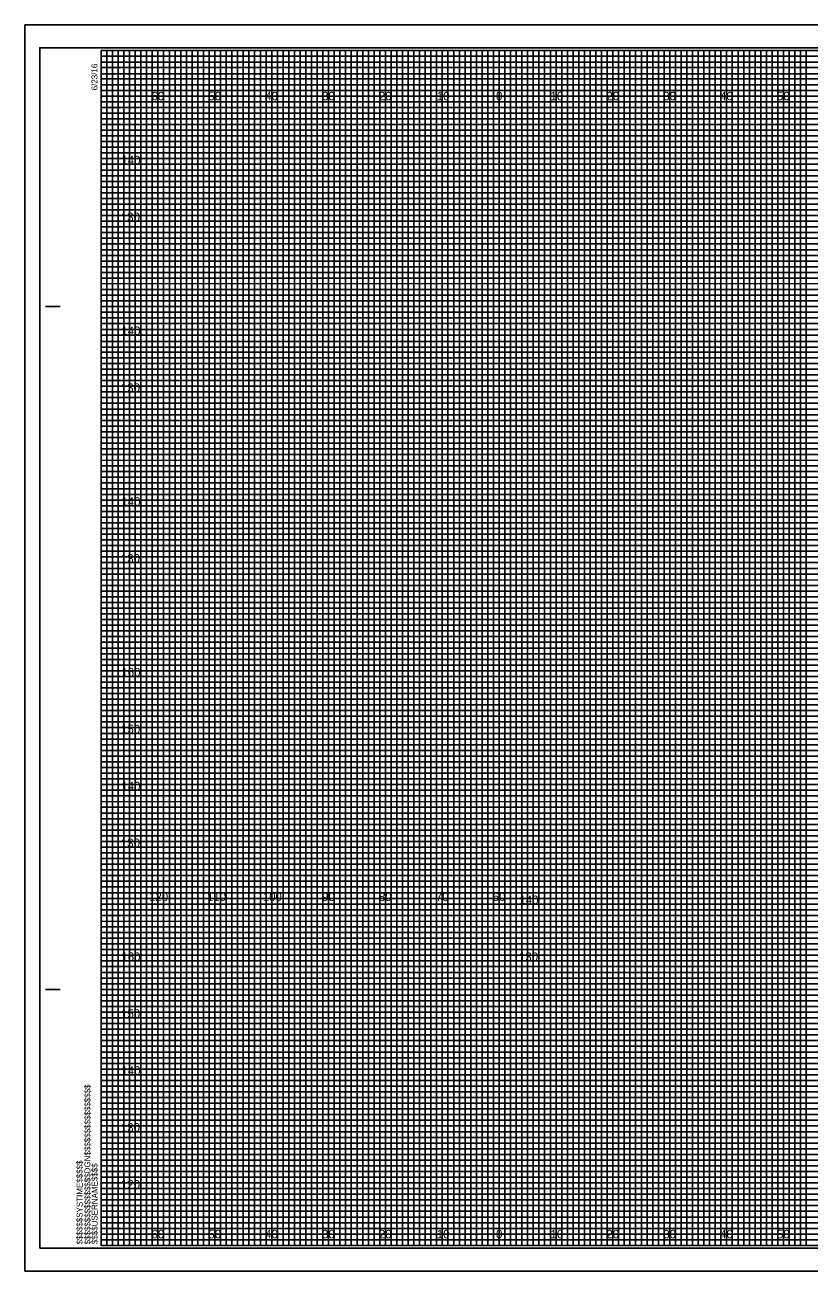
# Model space of a CAD drawing. Extents: x -13 to 323, y -5 to 3294.
# Drawn here: x -13.4 to 124.5, y 1535.5 to 1754.5 of the extents above; entities that cross this region are included whole.
import ezdxf

# ---------------------------------------------------------------- set-up
doc = ezdxf.new("R2010")
doc.units = 0
for name, color, linetype in [('Default', 7, 'Continuous'), ('Prop XS Elevation Labels', 7, 'Continuous'), ('Prop XS Offset Labels', 7, 'Continuous'), ('Scratch_Level_0', 7, 'Continuous'), ('Sheet Cross Section CELL', 7, 'Continuous'), ('Sheet Cross Section Grid Major CELL', 7, 'Continuous'), ('Sheet Cross Section Grid Middle CELL', 7, 'Continuous'), ('Sheet Cross Section Grid Minor 1 CELL', 7, 'Continuous'), ('Sheet Cross Section Grid Minor 2 CELL', 7, 'Continuous'), ('Sheet Cutting Line CELL', 7, 'Continuous'), ('Sheet DOT Grid CELL', 7, 'Continuous'), ('Sheet Plot Border Inside CELL', 7, 'Continuous'), ('Sheet Plot Border Outside CELL', 7, 'Continuous')]:
    doc.layers.add(name, color=color, linetype=linetype)

msp = doc.modelspace()

# ---------------------------------------------------------------- linework, layer by layer
at = {"layer": 'Default'}
msp.add_lwpolyline([(70, 1600), (10, 1600), (10, 1585), (70, 1585)], close=True, dxfattribs=at)
at = {"layer": 'Scratch_Level_0'}
for points in [[(310, 1730), (10, 1730), (10, 1710), (310, 1710)], [(310, 1700), (10, 1700), (10, 1680), (310, 1680)], [(310, 1670), (10, 1670), (10, 1650), (310, 1650)], [(315, 1640), (10, 1640), (10, 1605), (315, 1605)], [(310, 1590), (10, 1590), (10, 1555), (310, 1555)]]:
    msp.add_lwpolyline(points, close=True, dxfattribs=at)
at = {"layer": 'Sheet Cross Section CELL'}
for p, q in [((-9.8, 1705), (-7.3, 1705)), ((-9.7, 1705), (-7.2, 1705)), ((-9.8, 1585), (-7.3, 1585)), ((-9.7, 1585), (-7.2, 1585)), ((0, 1540), (0, 1540)), ((0, 1540), (0, 1540)), ((0, 1540), (0, 1540)), ((0, 1540), (0, 1540)), ((0, 1540), (0, 1540)), ((0, 1540), (0, 1540)), ((0, 1540), (0, 1540))]:
    msp.add_line(p, q, dxfattribs=at)
msp.add_lwpolyline([(320, 1750), (0, 1750), (0, 1540), (320, 1540)], close=True, dxfattribs=at)
at = {"layer": 'Sheet Cross Section Grid Major CELL'}
for p, q in [((10, 1750), (0, 1750)), ((10, 1540), (10, 1750)), ((30, 1750), (20, 1750)), ((20, 1750), (20, 1540)), ((30, 1540), (30, 1750)), ((50, 1750), (40, 1750)), ((40, 1750), (40, 1540)), ((50, 1540), (50, 1750)), ((70, 1750), (60, 1750)), ((60, 1750), (60, 1540)), ((70, 1540), (70, 1750)), ((90, 1750), (80, 1750)), ((80, 1750), (80, 1540)), ((90, 1540), (90, 1750)), ((110, 1750), (100, 1750)), ((100, 1750), (100, 1540)), ((110, 1540), (110, 1750)), ((130, 1750), (120, 1750)), ((120, 1750), (120, 1540)), ((20, 1540), (10, 1540)), ((40, 1540), (30, 1540)), ((60, 1540), (50, 1540)), ((80, 1540), (70, 1540)), ((100, 1540), (90, 1540)), ((120, 1540), (110, 1540))]:
    msp.add_line(p, q, dxfattribs=at)
for points in [[(0, 1740), (320, 1740), (320, 1730), (0, 1730)], [(0, 1720), (320, 1720), (320, 1710), (0, 1710)], [(0, 1700), (320, 1700), (320, 1690), (0, 1690)], [(0, 1680), (320, 1680), (320, 1670), (0, 1670)], [(0, 1660), (320, 1660), (320, 1650), (0, 1650)], [(0, 1640), (320, 1640), (320, 1630), (0, 1630)], [(0, 1620), (320, 1620), (320, 1610), (0, 1610)], [(0, 1600), (320, 1600), (320, 1590), (0, 1590)], [(0, 1580), (320, 1580), (320, 1570), (0, 1570)], [(0, 1560), (320, 1560), (320, 1550), (0, 1550)]]:
    msp.add_lwpolyline(points, dxfattribs=at)
at = {"layer": 'Sheet Cross Section Grid Middle CELL'}
for points in [[(0, 1750), (5, 1750), (5, 1540), (15, 1540), (15, 1750), (25, 1750), (25, 1540), (35, 1540), (35, 1750), (45, 1750), (45, 1540), (55, 1540), (55, 1750), (65, 1750), (65, 1540), (75, 1540), (75, 1750), (85, 1750), (85, 1540), (95, 1540), (95, 1750), (105, 1750), (105, 1540), (115, 1540), (115, 1750), (125, 1750)], [(0, 1745), (275, 1745)], [(0, 1725), (320, 1725), (320, 1735), (0, 1735)], [(0, 1705), (320, 1705), (320, 1715), (0, 1715)], [(0, 1685), (320, 1685), (320, 1695), (0, 1695)], [(0, 1665), (320, 1665), (320, 1675), (0, 1675)], [(0, 1645), (320, 1645), (320, 1655), (0, 1655)], [(0, 1625), (320, 1625), (320, 1635), (0, 1635)], [(0, 1605), (320, 1605), (320, 1615), (0, 1615)], [(0, 1585), (320, 1585), (320, 1595), (0, 1595)], [(0, 1565), (320, 1565), (320, 1575), (0, 1575)], [(0, 1545), (320, 1545), (320, 1555), (0, 1555)]]:
    msp.add_lwpolyline(points, dxfattribs=at)
at = {"layer": 'Sheet Cross Section Grid Minor 1 CELL'}
for p, q in [((0, 1749), (260, 1749)), ((260, 1747.98), (0, 1747.98)), ((0, 1747.98), (0, 1747)), ((0, 1747), (260, 1747)), ((260, 1745.89), (0, 1745.89)), ((0, 1745.89), (0, 1744)), ((0, 1744), (320, 1744))]:
    msp.add_line(p, q, dxfattribs=at)
for points in [[(0, 1743), (270, 1743), (320, 1743), (320, 1742), (0, 1742)], [(0, 1741), (320, 1741), (320, 1739), (0, 1739)], [(0, 1738), (320, 1738), (320, 1737), (0, 1736.98)], [(0, 1736), (320, 1736), (320, 1734), (0, 1734)], [(0, 1733), (320, 1733), (320, 1732), (0, 1732)], [(0, 1731), (320, 1731), (320, 1729), (0, 1729)], [(0, 1728), (320, 1728), (320, 1727), (0, 1727)], [(0, 1726), (320, 1726), (320, 1724), (0, 1724)], [(0, 1723), (320, 1723), (320, 1722), (0, 1722)], [(0, 1721), (320, 1721), (320, 1719), (0, 1719)], [(0, 1718), (320, 1718), (320, 1717), (0, 1717)], [(0, 1716), (320, 1716), (320, 1713.95), (320, 1713), (320, 1712), (0, 1712)], [(0, 1714), (320, 1714), (320, 1713), (0, 1713)], [(0, 1711), (320, 1711), (320, 1709), (0, 1709.03)], [(0, 1709.03), (320, 1709), (320, 1708), (0, 1708)], [(0, 1707), (320, 1707), (320, 1706), (0, 1706)], [(0, 1704), (320, 1704), (320, 1703), (0, 1703)], [(0, 1702), (320, 1702), (320, 1701), (0, 1701)], [(-0.07, 1698.89), (320, 1698.89), (320, 1697.88), (-0.07, 1697.88)], [(0, 1697), (320, 1697), (320, 1696), (0, 1696)], [(0, 1694), (320, 1694), (320, 1693), (0, 1693)], [(0, 1692), (320, 1692), (320, 1691), (0, 1691)], [(0, 1689), (320, 1689), (320, 1688), (0, 1688)], [(0, 1687), (320, 1687), (320, 1686), (0, 1686)], [(0, 1684), (320, 1684), (320, 1683), (0, 1683)], [(0, 1682), (320, 1682), (320, 1681), (0, 1681)], [(0, 1679), (320, 1679), (319.99, 1677.98), (0, 1678)], [(0, 1677), (320, 1677), (320, 1676), (0, 1676)], [(0, 1674), (320, 1674), (320, 1673), (0, 1673)], [(0, 1672), (320, 1672), (320, 1671), (0, 1671)], [(0, 1669), (320, 1669), (320, 1668), (0, 1668)], [(0, 1667), (320, 1667), (320, 1666), (0, 1666)], [(0, 1664), (320, 1664), (320, 1663), (0, 1663)], [(0, 1662), (320, 1662), (320, 1661), (0, 1661)], [(0, 1659), (320, 1659), (320, 1658), (0, 1658)], [(0, 1656.99), (320.07, 1656.91), (320, 1656), (0, 1656)], [(0, 1654), (320, 1654), (320, 1653), (0, 1653)], [(0, 1652), (320, 1652), (320, 1651), (0, 1651)], [(0, 1649), (320, 1649), (320, 1648), (0, 1648)], [(0, 1647), (320, 1647), (320, 1646), (0, 1646)], [(0, 1644), (320, 1644), (320, 1643), (0, 1643)], [(0, 1642), (320, 1642), (320, 1641), (0, 1641)], [(0, 1639), (320, 1639), (320, 1638), (0, 1638)], [(0, 1637), (320, 1637), (320, 1636), (0, 1636)], [(0, 1634), (320, 1634), (320, 1633), (0, 1633)], [(0, 1632), (320, 1632), (320, 1631), (0, 1631)], [(0, 1629), (320, 1629), (320, 1628), (0, 1628)], [(0, 1627), (320, 1627), (320, 1626), (0, 1626)], [(0, 1624), (320, 1624), (320, 1623), (0, 1623)], [(0, 1622), (320, 1622), (320, 1621), (0, 1621)], [(0, 1619), (320, 1619), (319.99, 1617.98), (0, 1618)], [(0, 1617), (320, 1617), (320, 1616), (0, 1616)], [(0, 1614), (320, 1614), (320, 1613), (0, 1613)], [(0, 1612), (320, 1612), (320, 1611), (0, 1611)], [(0, 1609), (320, 1609), (320, 1608), (0, 1608)], [(0, 1607), (320, 1607), (320, 1606), (0, 1606)], [(0, 1604), (320, 1604), (320, 1603), (0, 1603)], [(0, 1602), (320, 1602), (320, 1601), (0, 1601)], [(0, 1599), (320, 1599), (320, 1598), (0, 1598)], [(0, 1596.99), (320.07, 1596.91), (320, 1596), (0, 1596)], [(0, 1594), (320, 1594), (320, 1593), (0, 1593)], [(0, 1592), (320, 1592), (320, 1591), (0, 1591)], [(0, 1589), (320, 1589), (320, 1588), (0, 1588)], [(0, 1587), (320, 1587), (320, 1586), (0, 1586)], [(0, 1584), (320, 1584), (320, 1583), (0, 1583)], [(0, 1582), (320, 1582), (320, 1581), (0, 1581)], [(0, 1579), (320, 1579), (320, 1578), (0, 1578)], [(0, 1577), (320, 1577), (320, 1576), (0, 1576)], [(0, 1574), (320, 1574), (320, 1573), (0, 1573)], [(0, 1572), (320, 1572), (320, 1571), (0, 1571)], [(0, 1569), (320, 1569), (320, 1568), (0, 1568)], [(0, 1567), (320, 1567), (320, 1566), (0, 1566)], [(0, 1564), (320, 1564), (320, 1563), (0, 1563)], [(0, 1562), (320, 1562), (320, 1561), (0, 1561)], [(0, 1559), (320, 1559), (320, 1558), (0, 1558)], [(0, 1557), (320, 1557), (320, 1556), (0, 1556)], [(0, 1554), (320, 1554), (320, 1553), (0, 1553)], [(0, 1552), (320, 1552), (320, 1551), (0, 1551)], [(0, 1549), (320, 1549), (320, 1548), (0, 1548)], [(0, 1547), (320, 1547), (320, 1546), (0, 1546)], [(0, 1544), (320, 1544), (320, 1543), (0, 1543)], [(0, 1542), (320, 1542), (320, 1541), (0, 1541)]]:
    msp.add_lwpolyline(points, dxfattribs=at)
at = {"layer": 'Sheet Cross Section Grid Minor 2 CELL'}
for points in [[(0, 1540), (1, 1540), (1, 1750), (2, 1750), (2, 1540)], [(2, 1540), (3, 1540), (3, 1750), (4, 1750), (4, 1540)], [(5, 1540), (6, 1540), (6, 1750), (7, 1750), (7, 1540)], [(7, 1540), (8, 1540), (8, 1750), (9, 1750), (9, 1540)], [(10, 1540), (11, 1540), (11, 1750), (12, 1750), (12, 1540)], [(12, 1540), (13, 1540), (13, 1750), (14, 1750), (14, 1540)], [(15, 1540), (16, 1540), (16, 1750), (17, 1750), (17, 1540)], [(17, 1540), (18, 1540), (18, 1750), (19, 1750), (19, 1540)], [(20, 1540), (21, 1540), (21, 1750), (22, 1750), (22, 1540)], [(22, 1540), (23, 1540), (23, 1750), (24, 1750), (24, 1540)], [(25, 1540), (26, 1540), (26, 1750), (27, 1750), (27, 1540)], [(27, 1540), (28, 1540), (28, 1750), (29, 1750), (29, 1540)], [(30, 1540), (31, 1540), (31, 1750), (32, 1750), (32, 1540)], [(32, 1540), (33, 1540), (33, 1750), (34, 1750), (34, 1540)], [(35, 1540), (36, 1540), (36, 1750), (37, 1750), (37, 1540)], [(37, 1540), (38, 1540), (38, 1750), (39, 1750), (39, 1540)], [(40, 1540), (41, 1540), (41, 1750), (42, 1750), (42, 1540)], [(42, 1540), (43, 1540), (43, 1750), (44, 1750), (44, 1540)], [(45, 1540), (46, 1540), (46, 1750), (47, 1750), (47, 1540)], [(47, 1540), (48, 1540), (48, 1750), (49, 1750), (49, 1540)], [(50, 1540), (51, 1540), (51, 1750), (52, 1750), (52, 1540)], [(52, 1540), (53, 1540), (53, 1750), (54, 1750), (54, 1540)], [(55, 1540), (56, 1540), (56, 1750), (57, 1750), (57, 1540)], [(57, 1540), (58, 1540), (58, 1750), (59, 1750), (59, 1540)], [(60, 1540), (61, 1540), (61, 1750), (62, 1750), (62, 1540)], [(62, 1540), (63, 1540), (63, 1750), (64, 1750), (64, 1540)], [(65, 1540), (66, 1540), (66, 1750), (67, 1750), (67, 1540)], [(67, 1540), (68, 1540), (68, 1750), (69, 1750), (69, 1540)], [(70, 1540), (71, 1540), (71, 1750), (72, 1750), (72, 1540)], [(72, 1540), (73, 1540), (73, 1750), (74, 1750), (74, 1540)], [(75, 1540), (76, 1540), (76, 1750), (77, 1750), (77, 1540)], [(77, 1540), (78, 1540), (78, 1750), (79, 1750), (79, 1540)], [(80, 1540), (81, 1540), (81, 1750), (82, 1750), (82, 1540)], [(82, 1540), (83, 1540), (83, 1750), (84, 1750), (84, 1540)], [(85, 1540), (86, 1540), (86, 1750), (87, 1750), (87, 1540)], [(87, 1540), (88, 1540), (88, 1750), (89, 1750), (89, 1540)], [(90, 1540), (91, 1540), (91, 1750), (92, 1750), (92, 1540)], [(92, 1540), (93, 1540), (93, 1750), (94, 1750), (94, 1540)], [(95, 1540), (96, 1540), (96, 1750), (97, 1750), (97, 1540)], [(97, 1540), (98, 1540), (98, 1750), (99, 1750), (99, 1540)], [(100, 1540), (101, 1540), (101, 1750), (102, 1750), (102, 1540)], [(102, 1540), (103, 1540), (103, 1750), (104, 1750), (104, 1540)], [(105, 1540), (106, 1540), (106, 1750), (107, 1750), (107, 1540)], [(107, 1540), (108, 1540), (108, 1750), (109, 1750), (109, 1540)], [(110, 1540), (111, 1540), (111, 1750), (112, 1750), (112, 1540)], [(112, 1540), (113, 1540), (113, 1750), (114, 1750), (114, 1540)], [(115, 1540), (116, 1540), (116, 1750), (117, 1750), (117, 1540)], [(117, 1540), (118, 1540), (118, 1750), (119, 1750), (119, 1540)], [(120, 1540), (121, 1540), (121, 1750), (122, 1750), (122, 1540)], [(122, 1540), (123, 1540), (123, 1750), (124, 1750), (124, 1540)]]:
    msp.add_lwpolyline(points, dxfattribs=at)
at = {"layer": 'Sheet Cutting Line CELL'}
for p, q in [((323.3, 1754.5), (-13.4, 1754.5)), ((-13.4, 1754.5), (-13.4, 1535.5)), ((-13.4, 1535.5), (323.3, 1535.5))]:
    msp.add_line(p, q, dxfattribs=at)
at = {"layer": 'Sheet DOT Grid CELL'}
for p, q in [((10, 1540), (10, 1750)), ((20, 1540), (20, 1750)), ((30, 1540), (30, 1750)), ((40, 1540), (40, 1750)), ((50, 1540), (50, 1750)), ((60, 1540), (60, 1750)), ((70, 1540), (70, 1750)), ((80, 1540), (80, 1750)), ((90, 1540), (90, 1750)), ((100, 1540), (100, 1750)), ((110, 1540), (110, 1750)), ((120, 1540), (120, 1750)), ((0, 1740), (320, 1740)), ((0, 1730), (320, 1730)), ((0, 1720), (320, 1720)), ((0, 1710), (320, 1710)), ((0, 1700), (320, 1700)), ((0, 1690), (320, 1690)), ((0, 1680), (320, 1680)), ((0, 1670), (320, 1670)), ((0, 1660), (320, 1660)), ((0, 1650), (320, 1650)), ((0, 1640), (320, 1640)), ((0, 1630), (320, 1630)), ((0, 1620), (320, 1620)), ((0, 1610), (320, 1610)), ((0, 1600), (320, 1600)), ((0, 1590), (320, 1590)), ((0, 1580), (320, 1580)), ((0, 1570), (320, 1570)), ((0, 1560), (320, 1560)), ((0, 1550), (320, 1550))]:
    msp.add_line(p, q, dxfattribs=at)
at = {"layer": 'Sheet Plot Border Inside CELL'}
msp.add_lwpolyline([(-10.8, 1539.5), (322.4, 1539.5), (322.4, 1750.5), (-10.8, 1750.5)], close=True, dxfattribs=at)
at = {"layer": 'Sheet Plot Border Outside CELL'}
msp.add_lwpolyline([(-13.4, 1535.5), (323.3, 1535.5), (323.3, 1754.5), (-13.4, 1754.5)], close=True, dxfattribs=at)

# ---------------------------------------------------------------- texts
at = {"layer": 'Prop XS Elevation Labels'}
for s, p in [('140', (3.57, 1730)), ('130', (3.49, 1720)), ('140', (3.57, 1700)), ('130', (3.49, 1690)), ('140', (3.57, 1670)), ('130', (3.49, 1660)), ('160', (3.57, 1640)), ('150', (3.52, 1630)), ('140', (3.57, 1620)), ('130', (3.49, 1610)), ('140', (73.57, 1600)), ('160', (3.57, 1590)), ('130', (73.49, 1590)), ('150', (3.52, 1580)), ('140', (3.57, 1570)), ('130', (3.49, 1560)), ('120', (3.5, 1550))]:
    msp.add_text(s, height=1.5, dxfattribs=at).set_placement(p)
at = {"layer": 'Prop XS Offset Labels'}
for s, p in [('60', (8.86, 1741.25)), ('50', (18.86, 1741.25)), ('40', (28.86, 1741.25)), ('30', (38.86, 1741.25)), ('20', (48.86, 1741.25)), ('10', (59.04, 1741.25)), ('0', (69.45, 1741.25)), ('0', (69.45, 1741.25)), ('10', (79.04, 1741.25)), ('20', (88.86, 1741.25)), ('30', (98.86, 1741.25)), ('40', (108.86, 1741.25)), ('50', (118.86, 1741.25)), ('120', (8.44, 1600.52)), ('110', (18.62, 1600.52)), ('100', (28.44, 1600.52)), ('90', (38.86, 1600.52)), ('80', (48.86, 1600.52)), ('70', (58.86, 1600.52)), ('60', (68.86, 1600.52)), ('60', (8.86, 1541.25)), ('50', (18.86, 1541.25)), ('40', (28.86, 1541.25)), ('30', (38.86, 1541.25)), ('20', (48.86, 1541.25)), ('10', (59.04, 1541.25)), ('0', (69.45, 1541.25)), ('0', (69.45, 1541.25)), ('10', (79.04, 1541.25)), ('20', (88.86, 1541.25)), ('30', (98.86, 1541.25)), ('40', (108.86, 1541.25)), ('50', (118.86, 1541.25))]:
    msp.add_text(s, height=1.5, dxfattribs=at).set_placement(p)
at = {"layer": 'Sheet Cross Section CELL'}
for s, p in [('6/23/16', (-0.65, 1743)), ('$$$$$$$$$$$$$$$$DGN$$$$$$$$$$$$$$$$', (-1.88, 1540.18)), ('$$$$$$SYSTIME$$$$$', (-3.26, 1540.18)), ('$$$$USERNAME$$$$', (-0.62, 1540.23))]:
    msp.add_text(s, height=1.05, rotation=90, dxfattribs=at).set_placement(p)

doc.saveas('drawing.dxf')
